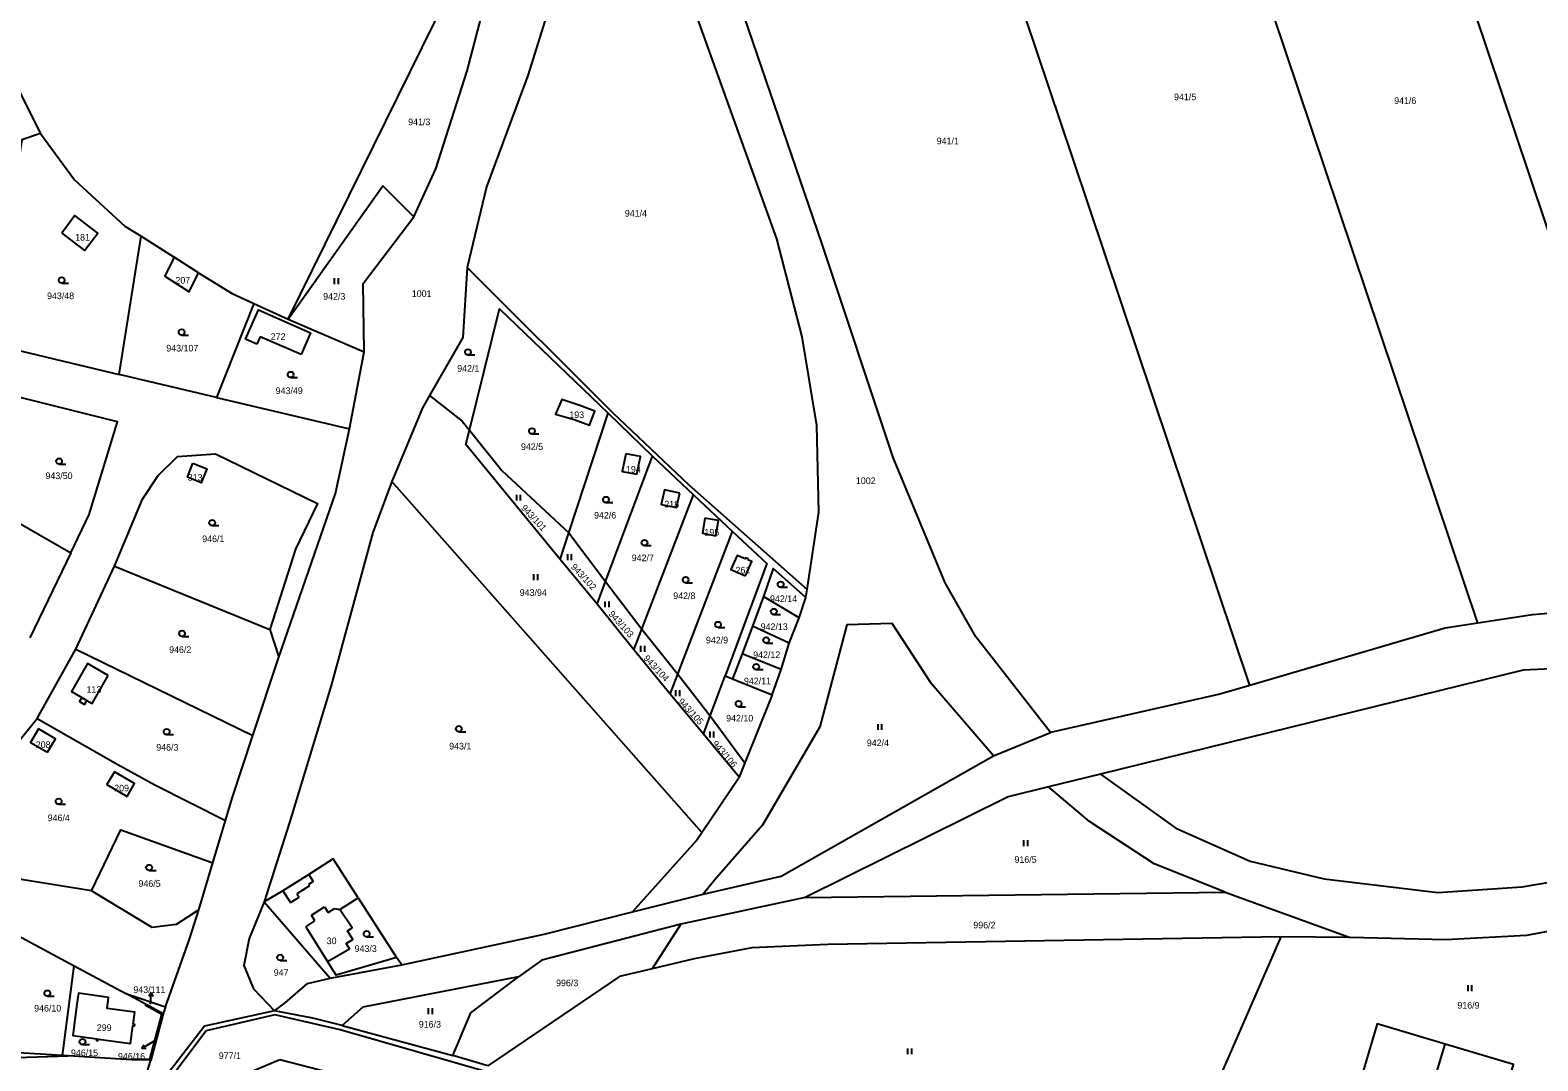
# Model space of a CAD drawing. Extents: x -751333 to -746055, y -1133395 to -1129777.
# Drawn here: x -750645.6 to -750258.6, y -1131231.7 to -1130967.2 of the extents above; entities that cross this region are included whole.
import ezdxf

# ---------------------------------------------------------------- set-up
doc = ezdxf.new("R2010")
doc.units = 0
for name, color, linetype in [('Hranice parcel', 7, 'Continuous'), ('Parcelní čísla', 7, 'Continuous'), ('Pop  PČ popisy', 7, 'Continuous'), ('Vnitřní kresba', 7, 'Continuous'), ('Značky kultur', 7, 'Continuous')]:
    doc.layers.add(name, color=color, linetype=linetype)

msp = doc.modelspace()

# ---------------------------------------------------------------- linework, layer by layer
at = {"layer": 'Hranice parcel'}
for p, q in [((-750653.79, -1130972.43), (-750642.94, -1130993.73)), ((-750622.78, -1131055.54), (-750617.17, -1131020.08)), ((-750617.17, -1131020.08), (-750608.62, -1131025.49)), ((-750602.38, -1131029.51), (-750608.62, -1131025.49)), ((-750588.24, -1131037.32), (-750597.78, -1131061.49)), ((-750588.24, -1131037.32), (-750579.43, -1131041.4)), ((-750579.43, -1131041.4), (-750559.85, -1131049.76)), ((-750563.69, -1131069.55), (-750559.85, -1131049.76)), ((-750597.78, -1131061.49), (-750622.78, -1131055.54)), ((-750597.78, -1131061.49), (-750563.69, -1131069.55)), ((-750507.32, -1131096.22), (-750497.27, -1131065.52)), ((-750497.27, -1131065.52), (-750485.87, -1131076.56)), ((-750497.91, -1131108.74), (-750485.87, -1131076.56)), ((-750485.87, -1131076.56), (-750475.37, -1131086.44)), ((-750473.19, -1131173.15), (-750552.77, -1131083.07)), ((-750658.73, -1131087.82), (-750635.2, -1131101.36)), ((-750488.61, -1131120.96), (-750475.37, -1131086.44)), ((-750475.37, -1131086.44), (-750465.29, -1131095.85)), ((-750509.57, -1131103.09), (-750507.32, -1131096.22)), ((-750507.32, -1131096.22), (-750497.91, -1131108.74)), ((-750479.38, -1131132.47), (-750465.29, -1131095.85)), ((-750635.2, -1131101.36), (-750645.75, -1131123.19)), ((-750633.92, -1131126.08), (-750623.98, -1131104.75)), ((-750623.98, -1131104.75), (-750584.08, -1131121.02)), ((-750500.08, -1131114.54), (-750509.57, -1131103.09)), ((-750500.08, -1131114.54), (-750497.91, -1131108.74)), ((-750497.91, -1131108.74), (-750488.61, -1131120.96)), ((-750457.41, -1131112.56), (-750460.24, -1131120.18)), ((-750448.23, -1131118.01), (-750457.41, -1131112.56)), ((-750446.53, -1131112.81), (-750446.13, -1131110.72)), ((-750490.63, -1131126.23), (-750500.08, -1131114.54)), ((-750448.23, -1131118.01), (-750446.53, -1131112.81)), ((-750460.24, -1131120.18), (-750462.82, -1131127.24)), ((-750450.77, -1131124.56), (-750460.24, -1131120.18)), ((-750450.77, -1131124.56), (-750448.23, -1131118.01)), ((-750584.08, -1131121.02), (-750581.77, -1131128.11)), ((-750490.63, -1131126.23), (-750488.61, -1131120.96)), ((-750488.61, -1131120.96), (-750479.38, -1131132.47)), ((-750643.85, -1131143.83), (-750633.92, -1131126.08)), ((-750633.92, -1131126.08), (-750588.48, -1131148.2)), ((-750588.48, -1131148.2), (-750581.77, -1131128.11)), ((-750481.37, -1131137.63), (-750490.63, -1131126.23)), ((-750462.82, -1131127.24), (-750465.37, -1131133.64)), ((-750452.87, -1131131.28), (-750462.82, -1131127.24)), ((-750452.87, -1131131.28), (-750450.77, -1131124.56)), ((-750455.14, -1131137.79), (-750452.87, -1131131.28)), ((-750481.37, -1131137.63), (-750479.38, -1131132.47)), ((-750479.38, -1131132.47), (-750471.07, -1131143.22)), ((-750471.07, -1131143.22), (-750467.23, -1131132.9)), ((-750467.23, -1131132.9), (-750465.37, -1131133.64)), ((-750465.37, -1131133.64), (-750455.14, -1131137.79)), ((-750472.81, -1131147.91), (-750481.37, -1131137.63)), ((-750455.14, -1131137.79), (-750462.15, -1131155.21)), ((-750472.81, -1131147.91), (-750471.07, -1131143.22)), ((-750471.07, -1131143.22), (-750462.15, -1131155.21)), ((-750398.36, -1131153.41), (-750383.69, -1131147.48)), ((-750463.62, -1131158.93), (-750472.81, -1131147.91)), ((-750473.19, -1131173.15), (-750463.62, -1131158.93)), ((-750370.85, -1131158.14), (-750384.23, -1131161.42)), ((-750598.74, -1131180.95), (-750595.5, -1131170.04)), ((-750602.36, -1131193.01), (-750598.74, -1131180.95)), ((-750580.75, -1131188.08), (-750585.52, -1131190.95)), ((-750566.12, -1131192.88), (-750561.42, -1131189.86)), ((-750561.42, -1131189.86), (-750551.57, -1131205.21)), ((-750491, -1131193.51), (-750472.83, -1131188.97)), ((-750446.64, -1131189.81), (-750478.58, -1131196.61)), ((-750446.64, -1131189.81), (-750338.88, -1131188.45)), ((-750338.88, -1131188.45), (-750306.79, -1131200.03)), ((-750663.9, -1131191.45), (-750634.31, -1131207.35)), ((-750585.52, -1131190.95), (-750568.64, -1131210.54)), ((-750478.58, -1131196.61), (-750485.93, -1131208.1)), ((-750324.56, -1131199.94), (-750360.45, -1131282.22)), ((-750306.79, -1131200.03), (-750324.56, -1131199.94)), ((-750550.24, -1131207.13), (-750551.57, -1131205.21)), ((-750637.34, -1131230.32), (-750634.31, -1131207.35)), ((-750634.31, -1131207.35), (-750621.05, -1131214.47)), ((-750568.64, -1131210.54), (-750550.24, -1131207.13)), ((-750615.88, -1131217.25), (-750621.05, -1131214.47)), ((-750621.05, -1131214.47), (-750610.86, -1131217.83)), ((-750611.5, -1131219.65), (-750615.88, -1131217.25)), ((-750611.5, -1131219.65), (-750614.64, -1131231.58)), ((-750610.86, -1131217.83), (-750611.5, -1131219.65)), ((-750565.51, -1131222.62), (-750537.12, -1131230.36)), ((-750637.34, -1131230.32), (-750676.72, -1131228.08)), ((-750292.72, -1131262.14), (-750282.4, -1131227.41)), ((-750635.87, -1131230.45), (-750637.34, -1131230.32)), ((-750619.64, -1131231.48), (-750635.87, -1131230.45)), ((-750614.64, -1131231.58), (-750619.64, -1131231.48)), ((-750617.63, -1131241.09), (-750614.64, -1131231.58)), ((-750528.14, -1131233.04), (-750537.12, -1131230.36))]:
    msp.add_line(p, q, dxfattribs=at)
for points in [[(-750332.51, -1131135.35), (-750377.98, -1131000.04), (-750423.45, -1130864.72)], [(-750274.04, -1131119.43), (-750316.73, -1130992.37), (-750359.42, -1130865.31)], [(-750223.88, -1131114.14), (-750264.62, -1130992.88), (-750305.36, -1130871.62)], [(-750383.69, -1131147.48), (-750402.83, -1131122.9), (-750410.73, -1131109.04), (-750424.07, -1131076.84), (-750442.36, -1131021.87), (-750466.73, -1130950.73), (-750487.24, -1130888.84), (-750489.98, -1130882.7)], [(-750579.43, -1131041.4), (-750541.82, -1130965.24), (-750511.43, -1130902.47)], [(-750547.16, -1131015.06), (-750541.48, -1131002.77), (-750533.47, -1130977.66), (-750525.19, -1130946.2), (-750513.6, -1130914.64), (-750511.43, -1130902.47)], [(-750495.43, -1130900.48), (-750502.66, -1130930.1), (-750517.9, -1130978.8), (-750528.5, -1131007.43), (-750533.48, -1131028.12)], [(-750446.13, -1131110.72), (-750443.13, -1131090.87), (-750443.7, -1131068.64), (-750447.41, -1131045.86), (-750453.97, -1131020.75), (-750476.26, -1130958.59), (-750488.96, -1130919.57), (-750495.43, -1130900.48)], [(-750642.94, -1130993.73), (-750647.77, -1130995.31), (-750656.09, -1131047.61), (-750622.78, -1131055.54)], [(-750642.94, -1130993.73), (-750634.22, -1131005.62), (-750621.28, -1131017.48), (-750617.17, -1131020.08)], [(-750579.43, -1131041.4), (-750555.12, -1131007.18), (-750547.16, -1131015.06)], [(-750637.46, -1131019.3), (-750631.68, -1131023.76), (-750628.24, -1131019.3), (-750634.13, -1131014.8), (-750637.46, -1131019.3)], [(-750559.85, -1131049.76), (-750560.14, -1131032.23), (-750547.16, -1131015.06)], [(-750608.62, -1131025.49), (-750611.05, -1131030.29), (-750604.82, -1131034.31), (-750602.38, -1131029.51)], [(-750602.38, -1131029.51), (-750593.96, -1131034.68), (-750588.24, -1131037.32)], [(-750533.48, -1131028.12), (-750534.57, -1131046.11), (-750543.09, -1131060.97)], [(-750533.48, -1131028.12), (-750496.07, -1131065.4), (-750476.55, -1131083.89), (-750446.13, -1131110.72)], [(-750587.42, -1131047.77), (-750590.31, -1131046.51), (-750587.05, -1131039), (-750573.69, -1131044.84), (-750576.08, -1131050.47)], [(-750532.86, -1131069.86), (-750525.13, -1131038.7), (-750497.27, -1131065.52)], [(-750576.08, -1131050.47), (-750586.62, -1131045.94), (-750587.42, -1131047.77)], [(-750635.2, -1131101.36), (-750630.48, -1131091.47), (-750623.21, -1131067.69), (-750651.64, -1131060.63)], [(-750543.09, -1131060.97), (-750544.92, -1131064.15), (-750552.77, -1131083.07)], [(-750543.09, -1131060.97), (-750534.76, -1131067.51), (-750532.86, -1131069.86)], [(-750504.56, -1131063.49), (-750509.16, -1131062.02), (-750510.79, -1131065.79), (-750506.01, -1131067.14), (-750502.06, -1131068.59), (-750500.68, -1131064.97), (-750504.56, -1131063.49)], [(-750581.77, -1131128.11), (-750567.23, -1131086.09), (-750563.69, -1131069.55)], [(-750509.57, -1131103.09), (-750533.78, -1131073.55), (-750532.86, -1131069.86)], [(-750532.86, -1131069.86), (-750524.54, -1131080.18), (-750507.32, -1131096.22)], [(-750623.98, -1131104.75), (-750616.75, -1131087.54), (-750612.73, -1131081.49), (-750607.8, -1131076.65), (-750598.04, -1131075.93), (-750571.89, -1131088.67), (-750577.49, -1131100.38), (-750584.08, -1131121.02)], [(-750492.72, -1131075.93), (-750493.64, -1131080.46), (-750489.87, -1131081.14), (-750488.93, -1131076.61), (-750492.72, -1131075.93)], [(-750603.83, -1131078.3), (-750600.26, -1131079.81), (-750601.72, -1131083.35), (-750605.26, -1131081.88), (-750603.83, -1131078.3)], [(-750552.77, -1131083.07), (-750557.65, -1131096.13), (-750568.36, -1131135.43), (-750579.01, -1131170.54), (-750585.52, -1131190.95)], [(-750478.89, -1131086.02), (-750482.83, -1131085.21), (-750483.68, -1131088.93), (-750479.74, -1131089.74), (-750478.89, -1131086.02)], [(-750472.41, -1131092.46), (-750473.07, -1131096.33), (-750469.61, -1131096.96), (-750468.91, -1131093.02), (-750472.41, -1131092.46)], [(-750465.29, -1131095.85), (-750456.53, -1131104.12), (-750467.23, -1131132.9)], [(-750461.4, -1131103.14), (-750461.28, -1131102.87), (-750461.99, -1131102.61), (-750462.09, -1131102.85), (-750464.13, -1131101.99), (-750465.72, -1131105.65), (-750461.99, -1131107.27)], [(-750461.99, -1131107.27), (-750460.34, -1131103.59), (-750461.4, -1131103.14)], [(-750446.53, -1131112.81), (-750454.86, -1131105.37), (-750457.41, -1131112.56)], [(-750223.88, -1131114.14), (-750259.94, -1131117.26), (-750274.04, -1131119.43)], [(-750398.36, -1131153.41), (-750414.23, -1131134.96), (-750424.36, -1131119.49), (-750435.97, -1131119.86), (-750442.91, -1131145.97), (-750457.63, -1131171.27), (-750469.94, -1131185.39), (-750472.83, -1131188.97)], [(-750370.85, -1131158.14), (-750351.54, -1131171.98), (-750332.45, -1131180.52), (-750313.48, -1131185.03), (-750284.31, -1131188.5), (-750262.6, -1131187.08), (-750237.96, -1131182.86), (-750198.96, -1131174.77), (-750007.37, -1131119.02)], [(-750007.37, -1131119.02), (-750096.89, -1131123.78), (-750262.33, -1131131.47), (-750370.85, -1131158.14)], [(-750274.04, -1131119.43), (-750282.4, -1131120.71), (-750332.51, -1131135.35)], [(-750625.57, -1131132.81), (-750630.88, -1131129.76), (-750635.02, -1131136.97), (-750632.39, -1131138.48), (-750632.98, -1131139.52), (-750631.64, -1131140.29), (-750631.05, -1131139.25), (-750629.72, -1131140.04), (-750625.57, -1131132.81)], [(-750332.51, -1131135.35), (-750340.2, -1131137.6), (-750383.69, -1131147.48)], [(-750629.89, -1131188.07), (-750647.96, -1131185.17), (-750660.39, -1131170.67), (-750661.43, -1131165.52), (-750643.85, -1131143.83)], [(-750641.17, -1131152.51), (-750639.14, -1131149.06), (-750643.44, -1131146.53), (-750645.5, -1131150.03), (-750641.17, -1131152.51)], [(-750643.85, -1131143.83), (-750623.08, -1131155.63), (-750613.63, -1131160.87), (-750595.5, -1131170.04)], [(-750595.5, -1131170.04), (-750593.76, -1131164.33), (-750588.48, -1131148.2)], [(-750472.83, -1131188.97), (-750452.8, -1131184.37), (-750398.36, -1131153.41)], [(-750462.15, -1131155.21), (-750463.19, -1131157.85), (-750463.62, -1131158.93)], [(-750624.01, -1131157.51), (-750625.92, -1131160.82), (-750620.73, -1131163.85), (-750618.82, -1131160.58), (-750624.01, -1131157.51)], [(-750384.23, -1131161.42), (-750394.55, -1131163.95), (-750446.64, -1131189.81)], [(-750338.88, -1131188.45), (-750357.11, -1131181.19), (-750373.67, -1131170.27), (-750384.23, -1131161.42)], [(-750629.89, -1131188.07), (-750622.31, -1131172.46), (-750598.74, -1131180.95)], [(-750491, -1131193.51), (-750474.63, -1131175.29), (-750473.19, -1131173.15)], [(-750561.42, -1131189.86), (-750567.81, -1131179.9), (-750574.13, -1131183.9), (-750580.75, -1131188.08)], [(-750602.36, -1131193.01), (-750608.11, -1131196.71), (-750614.32, -1131197.54), (-750629.89, -1131188.07)], [(-750213.06, -1131188.66), (-750241.04, -1131195.74), (-750261.52, -1131199.54), (-750282.31, -1131200.69), (-750306.79, -1131200.03)], [(-750610.86, -1131217.83), (-750604.75, -1131200.5), (-750602.36, -1131193.01)], [(-750585.52, -1131190.95), (-750589.37, -1131200.29), (-750590.81, -1131207.27), (-750588.28, -1131213.22), (-750582.93, -1131218.86)], [(-750551.57, -1131205.21), (-750567.07, -1131209.71), (-750569.3, -1131206.19), (-750563.67, -1131202.94), (-750564.53, -1131201.59), (-750562.76, -1131200.55), (-750564.16, -1131198.33), (-750562.99, -1131197.56), (-750566.12, -1131192.88)], [(-750550.24, -1131207.13), (-750513.65, -1131199.22), (-750491, -1131193.51)], [(-750478.58, -1131196.61), (-750514.29, -1131205.87), (-750520.23, -1131210.17)], [(-750324.56, -1131199.94), (-750440.85, -1131201.86), (-750460.37, -1131202.74), (-750475.17, -1131205.54), (-750485.93, -1131208.1)], [(-750485.93, -1131208.1), (-750494.34, -1131210.1), (-750520.95, -1131228.16), (-750523.07, -1131229.6), (-750528.14, -1131233.04)], [(-750582.93, -1131218.86), (-750580.15, -1131216.88), (-750574.41, -1131211.88), (-750568.64, -1131210.54)], [(-750520.23, -1131210.17), (-750560.2, -1131217.92), (-750565.51, -1131222.62)], [(-750537.12, -1131230.36), (-750535.86, -1131227.39), (-750535.03, -1131225.44), (-750532.48, -1131219.42), (-750520.23, -1131210.17)], [(-750628.17, -1131226.54), (-750628.11, -1131226.14), (-750619.86, -1131227.28), (-750619.23, -1131222.73), (-750618.83, -1131222.78), (-750618.78, -1131222.38), (-750619.17, -1131222.33), (-750618.75, -1131219.27), (-750625.88, -1131218.29), (-750625.49, -1131215.43), (-750633.21, -1131214.37), (-750633.6, -1131217.22), (-750634.7, -1131225.23), (-750628.5, -1131226.09), (-750628.56, -1131226.48), (-750628.17, -1131226.54)], [(-750619.64, -1131231.48), (-750619.63, -1131231.18), (-750614.87, -1131231.27), (-750611.85, -1131219.8), (-750616.03, -1131217.51), (-750615.88, -1131217.25)], [(-750582.93, -1131218.86), (-750600.91, -1131222.79), (-750618.46, -1131245.66)], [(-750565.51, -1131222.62), (-750573.02, -1131220.81), (-750582.93, -1131218.86)], [(-750818.16, -1131224.81), (-750709.78, -1131231), (-750659.74, -1131231.2), (-750635.87, -1131230.45)], [(-750282.4, -1131227.41), (-750299.84, -1131222.2), (-750310.14, -1131256.86)], [(-750275.17, -1131267.37), (-750264.83, -1131232.64), (-750282.4, -1131227.41)]]:
    msp.add_lwpolyline(points, dxfattribs=at)
at = {"layer": 'Pop  PČ popisy'}
for p, q in [((-750614.583, -1131214.203), (-750615.135, -1131215.177)), ((-750614.74, -1131217.2), (-750614.583, -1131214.203)), ((-750614.583, -1131214.203), (-750614.135, -1131215.229)), ((-750614.38, -1131227.04), (-750616.979, -1131228.54)), ((-750616.979, -1131228.54), (-750616.362, -1131227.606)), ((-750616.979, -1131228.54), (-750615.861, -1131228.473)), ((-750613.36, -1131226.46), (-750614.38, -1131227.04))]:
    msp.add_line(p, q, dxfattribs=at)
at = {"layer": 'Vnitřní kresba'}
for p, q in [((-750632.39, -1131138.48), (-750631.05, -1131139.25)), ((-750573.01, -1131185.68), (-750574.2, -1131186.43)), ((-750574.13, -1131183.9), (-750573.01, -1131185.68)), ((-750580.75, -1131188.08), (-750578.82, -1131191.13)), ((-750578.82, -1131191.13), (-750576.61, -1131189.74)), ((-750573.93, -1131186.85), (-750577.15, -1131188.89)), ((-750577.15, -1131188.89), (-750576.61, -1131189.74)), ((-750574.2, -1131186.43), (-750573.93, -1131186.85)), ((-750573.44, -1131194.38), (-750570.05, -1131192.24)), ((-750570.05, -1131192.24), (-750569.14, -1131193.68)), ((-750569.14, -1131193.68), (-750567.53, -1131192.65)), ((-750567.53, -1131192.65), (-750566.12, -1131192.88)), ((-750574.9, -1131197.33), (-750572.53, -1131195.82)), ((-750574.9, -1131197.33), (-750569.3, -1131206.19)), ((-750572.53, -1131195.82), (-750573.44, -1131194.38)), ((-750582.84, -1131219.92), (-750600.48, -1131224.07)), ((-750566.04, -1131223.81), (-750582.84, -1131219.92)), ((-750600.48, -1131224.07), (-750617.99, -1131247.26)), ((-750506.88, -1131240.71), (-750566.04, -1131223.81)), ((-750581.51, -1131231.45), (-750591.91, -1131235.86)), ((-750553.71, -1131238.62), (-750581.51, -1131231.45))]:
    msp.add_line(p, q, dxfattribs=at)
at = {"layer": 'Značky kultur'}
for p, q in [((-750567.481, -1131032.38), (-750567.481, -1131030.88)), ((-750566.48, -1131032.38), (-750566.48, -1131030.88)), ((-750637.533, -1131032.11), (-750635.783, -1131032.11)), ((-750606.743, -1131045.43), (-750604.993, -1131045.43)), ((-750533.243, -1131050.56), (-750531.493, -1131050.56)), ((-750578.763, -1131056.35), (-750577.013, -1131056.35)), ((-750516.813, -1131070.83), (-750515.063, -1131070.83)), ((-750638.203, -1131078.59), (-750636.453, -1131078.59)), ((-750520.731, -1131087.95), (-750520.731, -1131086.45)), ((-750519.73, -1131087.95), (-750519.73, -1131086.45)), ((-750497.813, -1131088.44), (-750496.063, -1131088.44)), ((-750598.903, -1131094.36), (-750597.153, -1131094.36)), ((-750487.943, -1131099.49), (-750486.193, -1131099.49)), ((-750507.641, -1131103.22), (-750507.641, -1131101.72)), ((-750506.64, -1131103.22), (-750506.64, -1131101.72)), ((-750516.341, -1131108.35), (-750516.341, -1131106.85)), ((-750515.34, -1131108.35), (-750515.34, -1131106.85)), ((-750477.363, -1131109.02), (-750475.613, -1131109.02)), ((-750452.973, -1131110.19), (-750451.223, -1131110.19)), ((-750498.001, -1131115.31), (-750498.001, -1131113.81)), ((-750497, -1131115.31), (-750497, -1131113.81)), ((-750454.733, -1131117.19), (-750452.983, -1131117.19)), ((-750606.633, -1131122.79), (-750604.883, -1131122.79)), ((-750469.043, -1131120.52), (-750467.293, -1131120.52)), ((-750488.871, -1131126.72), (-750488.871, -1131125.22)), ((-750487.87, -1131126.72), (-750487.87, -1131125.22)), ((-750456.693, -1131124.51), (-750454.943, -1131124.51)), ((-750459.243, -1131131.32), (-750457.493, -1131131.32)), ((-750479.891, -1131138.1), (-750479.891, -1131136.6)), ((-750478.89, -1131138.1), (-750478.89, -1131136.6)), ((-750463.763, -1131140.83), (-750462.013, -1131140.83)), ((-750535.563, -1131147.27), (-750533.813, -1131147.27)), ((-750471.091, -1131148.71), (-750471.091, -1131147.21)), ((-750470.09, -1131148.71), (-750470.09, -1131147.21)), ((-750427.961, -1131146.79), (-750427.961, -1131145.29)), ((-750426.96, -1131146.79), (-750426.96, -1131145.29)), ((-750610.583, -1131148.01), (-750608.833, -1131148.01)), ((-750638.303, -1131165.89), (-750636.553, -1131165.89)), ((-750390.561, -1131176.61), (-750390.561, -1131175.11)), ((-750389.56, -1131176.61), (-750389.56, -1131175.11)), ((-750615.053, -1131182.89), (-750613.303, -1131182.89)), ((-750559.243, -1131199.89), (-750557.493, -1131199.89)), ((-750581.443, -1131205.97), (-750579.693, -1131205.97)), ((-750276.511, -1131213.81), (-750276.511, -1131212.31)), ((-750275.51, -1131213.81), (-750275.51, -1131212.31)), ((-750641.213, -1131215.14), (-750639.463, -1131215.14)), ((-750543.361, -1131219.73), (-750543.361, -1131218.23)), ((-750542.36, -1131219.73), (-750542.36, -1131218.23)), ((-750632.183, -1131227.57), (-750630.433, -1131227.57)), ((-750420.331, -1131230.02), (-750420.331, -1131228.52)), ((-750419.33, -1131230.02), (-750419.33, -1131228.52))]:
    msp.add_line(p, q, dxfattribs=at)
for centre in [(-750637.533, -1131031.36), (-750606.743, -1131044.68), (-750533.243, -1131049.81), (-750578.763, -1131055.6), (-750516.813, -1131070.08), (-750638.203, -1131077.84), (-750497.813, -1131087.69), (-750598.903, -1131093.61), (-750487.943, -1131098.74), (-750477.363, -1131108.27), (-750452.973, -1131109.44), (-750454.733, -1131116.44), (-750469.043, -1131119.77), (-750606.633, -1131122.04), (-750456.693, -1131123.76), (-750459.243, -1131130.57), (-750463.763, -1131140.08), (-750610.583, -1131147.26), (-750535.563, -1131146.52), (-750638.303, -1131165.14), (-750615.053, -1131182.14), (-750559.243, -1131199.14), (-750581.443, -1131205.22), (-750641.213, -1131214.39), (-750632.183, -1131226.82)]:
    msp.add_circle(centre, 0.75, dxfattribs=at)

# ---------------------------------------------------------------- texts
at = {"layer": 'Parcelní čísla'}
for s, p in [('941/5', (-750351.978, -1130985.164)), ('941/6', (-750295.488, -1130986.124)), ('941/3', (-750548.59, -1130991.58)), ('941/1', (-750412.908, -1130996.474)), ('941/4', (-750492.97, -1131015.06)), ('181', (-750634.07, -1131021.19)), ('207', (-750608.33, -1131032.23)), ('943/48', (-750641.28, -1131036.23)), ('942/3', (-750570.41, -1131036.38)), ('1001', (-750547.65, -1131035.67)), ('272', (-750583.87, -1131046.69)), ('943/107', (-750610.67, -1131049.66)), ('942/1', (-750536, -1131054.85)), ('943/49', (-750582.6, -1131060.57)), ('193', (-750507.22, -1131066.76)), ('942/5', (-750519.64, -1131074.94)), ('943/50', (-750641.69, -1131082.41)), ('313', (-750605.175, -1131082.83)), ('194', (-750492.68, -1131080.75)), ('1002', (-750433.65, -1131083.69)), ('218', (-750482.83, -1131089.69)), ('942/6', (-750500.87, -1131092.54)), ('946/1', (-750601.46, -1131098.59)), ('195', (-750472.54, -1131096.9)), ('942/7', (-750491.2, -1131103.48)), ('261', (-750464.56, -1131106.64)), ('943/94', (-750519.95, -1131112.39)), ('942/8', (-750480.54, -1131113.21)), ('942/14', (-750455.7, -1131113.97)), ('942/13', (-750458.1, -1131121.15)), ('942/9', (-750472.15, -1131124.59)), ('946/2', (-750609.95, -1131127.03)), ('942/12', (-750460.03, -1131128.36)), ('113', (-750631.15, -1131137.27)), ('942/11', (-750462.4, -1131135.09)), ('942/10', (-750466.96, -1131144.63)), ('208', (-750644.19, -1131151.43)), ('946/3', (-750613.25, -1131152.11)), ('943/1', (-750538.06, -1131151.81)), ('942/4', (-750430.85, -1131150.96)), ('209', (-750624.05, -1131162.58)), ('946/4', (-750641.12, -1131170.21)), ('916/5', (-750392.95, -1131180.91)), ('946/5', (-750617.81, -1131187.06)), ('996/2', (-750403.51, -1131197.74)), ('30', (-750569.5, -1131201.78)), ('943/3', (-750562.33, -1131203.77)), ('947', (-750583.1, -1131209.91)), ('943/111', (-750619.126, -1131214.31)), ('996/3', (-750510.62, -1131212.58)), ('916/9', (-750279.26, -1131218.32)), ('946/10', (-750644.6, -1131219.07)), ('299', (-750628.51, -1131224.06)), ('916/3', (-750545.86, -1131223.2)), ('946/15', (-750635.147, -1131230.52)), ('946/16', (-750623.077, -1131231.44)), ('977/1', (-750597.208, -1131231.25))]:
    msp.add_text(s, height=1.7, dxfattribs=at).set_placement(p)
for s, rotation, p in [('943/101', 313, (-750519.741, -1131089.929)), ('943/102', 313, (-750506.941, -1131105.089)), ('943/103', 312, (-750497.271, -1131117.158)), ('943/104', 313, (-750488.301, -1131128.539)), ('943/105', 313, (-750479.441, -1131139.639)), ('943/106', 311, (-750470.691, -1131150.437))]:
    msp.add_text(s, height=1.7, rotation=rotation, dxfattribs=at).set_placement(p)

doc.saveas('drawing.dxf')
